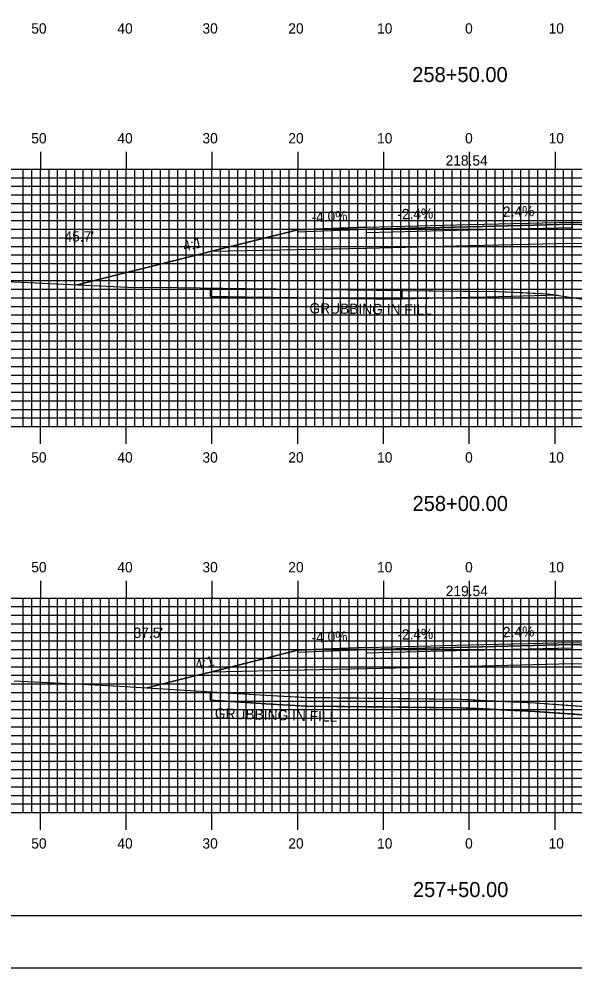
# Model space of a CAD drawing. Extents: x 1805471 to 1805814, y 442591 to 442811.
# Drawn here: x 1805584.2 to 1805648.9, y 442590.5 to 442701.2 of the extents above; entities that cross this region are included whole.
import ezdxf

# ---------------------------------------------------------------- set-up
doc = ezdxf.new("R2010")
doc.units = 0
for name, color, linetype in [('ANNOTATION', 7, 'Continuous'), ('BORDER', 7, 'Continuous'), ('D_Roadway_Centerline', 7, 'Continuous'), ('D_Roadway_Centerline_Text', 7, 'Continuous'), ('D_Roadway_Edge_Shoulder', 7, 'Continuous'), ('D_Roadway_Edge_TW', 7, 'Continuous'), ('D_Roadway_Pavement', 7, 'Continuous'), ('D_Roadway_SlopeLines', 7, 'Continuous'), ('D_Roadway_SubGrade', 7, 'Continuous'), ('D_Text_Standard', 7, 'Continuous'), ('GRUBBING IN FILL', 7, 'Continuous'), ('H_V ANNOTATION', 7, 'Continuous'), ('MAJOR', 7, 'Continuous'), ('MINOR', 7, 'Continuous'), ('PLOT BOUNDARY', 7, 'Continuous'), ('S_Roadway_Centerline', 7, 'Continuous')]:
    doc.layers.add(name, color=color, linetype=linetype)

msp = doc.modelspace()

# ---------------------------------------------------------------- linework, layer by layer
at = {"layer": 'BORDER'}
msp.add_lwpolyline([(1805487.11, 442596.67), (1805807.11, 442596.67), (1805807.11, 442806.67), (1805487.11, 442806.67)], close=True, dxfattribs=at)
at = {"layer": 'D_Roadway_Centerline'}
for points in [[(1805591.01, 442670.17), (1805604.71, 442673.6), (1805606.53, 442674.05), (1805616.71, 442676.6), (1805624.71, 442676.92), (1805636.71, 442677.21), (1805648.71, 442677.49), (1805656.71, 442677.17), (1805666.88, 442674.63), (1805668.71, 442674.17), (1805688.33, 442667.63)], [(1805599.16, 442623.21), (1805604.71, 442624.6), (1805606.53, 442625.05), (1805616.71, 442627.6), (1805624.71, 442627.92), (1805636.71, 442628.21), (1805648.71, 442628.49), (1805656.71, 442628.17), (1805666.88, 442625.63), (1805668.71, 442625.17), (1805684.65, 442619.86)]]:
    msp.add_lwpolyline(points, dxfattribs=at)
at = {"layer": 'D_Roadway_Edge_Shoulder'}
for points in [[(1805624.71, 442676.92), (1805616.71, 442676.6), (1805616.71, 442676.35), (1805624.71, 442676.67)], [(1805648.71, 442677.49), (1805656.71, 442677.17), (1805656.71, 442676.92), (1805648.71, 442677.24)], [(1805648.71, 442628.49), (1805656.71, 442628.17), (1805656.71, 442627.92), (1805648.71, 442628.24)], [(1805624.71, 442627.92), (1805616.71, 442627.6), (1805616.71, 442627.35), (1805624.71, 442627.67)]]:
    msp.add_lwpolyline(points, close=True, dxfattribs=at)
at = {"layer": 'D_Roadway_Edge_TW'}
for points in [[(1805624.71, 442676.67), (1805624.71, 442676.92), (1805636.71, 442677.21), (1805648.71, 442677.49), (1805648.71, 442677.24), (1805636.71, 442676.96)], [(1805624.71, 442627.67), (1805624.71, 442627.92), (1805636.71, 442628.21), (1805648.71, 442628.49), (1805648.71, 442628.24), (1805636.71, 442627.96)]]:
    msp.add_lwpolyline(points, close=True, dxfattribs=at)
at = {"layer": 'D_Roadway_Pavement'}
for points in [[(1805624.71, 442676.25), (1805624.71, 442676.67), (1805636.71, 442676.96), (1805648.71, 442677.24), (1805648.71, 442676.83), (1805636.71, 442676.54)], [(1805624.71, 442627.25), (1805624.71, 442627.67), (1805636.71, 442627.96), (1805648.71, 442628.24), (1805648.71, 442627.83), (1805636.71, 442627.54)]]:
    msp.add_lwpolyline(points, close=True, dxfattribs=at)
at = {"layer": 'D_Roadway_SlopeLines'}
for points in [[(1805616.71, 442676.6), (1805606.53, 442674.05), (1805604.71, 442673.6), (1805591.01, 442670.17)], [(1805616.71, 442627.6), (1805606.53, 442625.05), (1805604.71, 442624.6), (1805599.16, 442623.21)]]:
    msp.add_lwpolyline(points, dxfattribs=at)
at = {"layer": 'D_Roadway_SubGrade'}
for points in [[(1805624.71, 442674.42), (1805606.53, 442674.05), (1805616.71, 442676.6), (1805616.71, 442676.35), (1805624.71, 442676.67), (1805636.71, 442676.96), (1805648.71, 442677.24), (1805656.71, 442676.92), (1805656.71, 442677.17), (1805666.88, 442674.63), (1805648.71, 442674.99), (1805636.71, 442674.71)], [(1805624.71, 442625.42), (1805606.53, 442625.05), (1805616.71, 442627.6), (1805616.71, 442627.35), (1805624.71, 442627.67), (1805636.71, 442627.96), (1805648.71, 442628.24), (1805656.71, 442627.92), (1805656.71, 442628.17), (1805666.88, 442625.63), (1805648.71, 442625.99), (1805636.71, 442625.71)]]:
    msp.add_lwpolyline(points, close=True, dxfattribs=at)
at = {"layer": 'GRUBBING IN FILL'}
for p, q in [((1805606.53, 442669.81), (1805606.53, 442668.81)), ((1805606.53, 442669.81), (1805606.53, 442668.81)), ((1805628.84, 442669.52), (1805628.84, 442668.52)), ((1805628.84, 442669.52), (1805628.84, 442668.52)), ((1805606.53, 442622.76), (1805606.53, 442621.76)), ((1805606.53, 442622.76), (1805606.53, 442621.76))]:
    msp.add_line(p, q, dxfattribs=at)
for points in [[(1805606.53, 442669.81), (1805610.57, 442669.76), (1805621.29, 442669.62), (1805628.84, 442669.52), (1805636.03, 442669.44), (1805636.71, 442669.44), (1805636.71, 442668.71), (1805628.84, 442668.52), (1805619.7, 442668.64), (1805610.55, 442668.76), (1805606.53, 442668.81)], [(1805606.53, 442669.81), (1805610.57, 442669.76), (1805621.29, 442669.62), (1805628.84, 442669.52), (1805636.03, 442669.44), (1805636.71, 442669.44), (1805636.71, 442668.71), (1805628.84, 442668.52), (1805619.7, 442668.64), (1805610.55, 442668.76), (1805606.53, 442668.81)], [(1805636.71, 442669.44), (1805640.06, 442669.41), (1805642.96, 442669.28), (1805645.87, 442669.15), (1805647.09, 442668.96), (1805638.78, 442668.76), (1805636.71, 442668.71)], [(1805636.71, 442669.44), (1805640.06, 442669.41), (1805642.96, 442669.28), (1805645.87, 442669.15), (1805647.09, 442668.96), (1805638.78, 442668.76), (1805636.71, 442668.71)], [(1805606.53, 442622.76), (1805613.64, 442622.32), (1805617.38, 442622.1), (1805626.67, 442621.99), (1805635.61, 442621.89), (1805636.71, 442621.83), (1805636.71, 442620.83), (1805635.58, 442620.89), (1805626.64, 442620.99), (1805617.7, 442621.08), (1805613.58, 442621.32), (1805606.53, 442621.76)], [(1805606.53, 442622.76), (1805613.64, 442622.32), (1805617.38, 442622.1), (1805626.67, 442621.99), (1805635.61, 442621.89), (1805636.71, 442621.83), (1805636.71, 442620.83), (1805635.58, 442620.89), (1805626.64, 442620.99), (1805617.7, 442621.08), (1805613.58, 442621.32), (1805606.53, 442621.76)], [(1805636.71, 442621.83), (1805640.01, 442621.67), (1805644.4, 442621.44), (1805649.07, 442621.12), (1805653.73, 442620.8), (1805657.78, 442620.82), (1805661.83, 442620.83), (1805665.24, 442620.69), (1805666.88, 442620.62), (1805666.88, 442619.62), (1805664.35, 442619.73), (1805661.81, 442619.83), (1805657.76, 442619.82), (1805653.7, 442619.8), (1805649.02, 442620.12), (1805644.34, 442620.45), (1805639.96, 442620.67), (1805636.71, 442620.83)], [(1805636.71, 442621.83), (1805640.01, 442621.67), (1805644.4, 442621.44), (1805649.07, 442621.12), (1805653.73, 442620.8), (1805657.78, 442620.82), (1805661.83, 442620.83), (1805665.24, 442620.69), (1805666.88, 442620.62), (1805666.88, 442619.62), (1805664.35, 442619.73), (1805661.81, 442619.83), (1805657.76, 442619.82), (1805653.7, 442619.8), (1805649.02, 442620.12), (1805644.34, 442620.45), (1805639.96, 442620.67), (1805636.71, 442620.83)]]:
    msp.add_lwpolyline(points, close=True, dxfattribs=at)
for points in [[(1805606.53, 442668.81), (1805610.55, 442668.76), (1805628.84, 442668.52)], [(1805606.53, 442668.81), (1805610.55, 442668.76), (1805628.84, 442668.52)], [(1805606.53, 442621.76), (1805613.58, 442621.32), (1805617.1, 442621.11), (1805617.34, 442621.1), (1805617.7, 442621.08), (1805635.58, 442620.89), (1805644.34, 442620.45), (1805653.7, 442619.8), (1805661.81, 442619.83), (1805666.88, 442619.62)], [(1805606.53, 442621.76), (1805613.58, 442621.32), (1805617.1, 442621.11), (1805617.34, 442621.1), (1805617.7, 442621.08), (1805635.58, 442620.89), (1805644.34, 442620.45), (1805653.7, 442619.8), (1805661.81, 442619.83), (1805666.88, 442619.62)]]:
    msp.add_lwpolyline(points, dxfattribs=at)
at = {"layer": 'MAJOR'}
for p, q in [((1805586.71, 442685.67), (1805586.71, 442683.67)), ((1805596.71, 442685.67), (1805596.71, 442683.67)), ((1805606.71, 442685.67), (1805606.71, 442683.67)), ((1805616.71, 442685.67), (1805616.71, 442683.67)), ((1805626.71, 442685.67), (1805626.71, 442683.67)), ((1805636.71, 442685.67), (1805636.71, 442683.67)), ((1805646.71, 442685.67), (1805646.71, 442683.67)), ((1805496.71, 442683.67), (1805776.71, 442683.67)), ((1805496.71, 442683.67), (1805776.71, 442683.67)), ((1805586.71, 442653.67), (1805586.71, 442683.67)), ((1805596.71, 442653.67), (1805596.71, 442683.67)), ((1805606.71, 442653.67), (1805606.71, 442683.67)), ((1805616.71, 442653.67), (1805616.71, 442683.67)), ((1805626.71, 442653.67), (1805626.71, 442683.67)), ((1805636.71, 442653.67), (1805636.71, 442683.67)), ((1805646.71, 442653.67), (1805646.71, 442683.67)), ((1805496.71, 442678.67), (1805776.71, 442678.67)), ((1805496.71, 442673.67), (1805776.71, 442673.67)), ((1805496.71, 442668.67), (1805776.71, 442668.67)), ((1805496.71, 442663.67), (1805776.71, 442663.67)), ((1805496.71, 442658.67), (1805776.71, 442658.67)), ((1805496.71, 442653.67), (1805776.71, 442653.67)), ((1805496.71, 442653.67), (1805776.71, 442653.67)), ((1805586.71, 442651.66), (1805586.71, 442653.67)), ((1805596.71, 442651.66), (1805596.71, 442653.67)), ((1805606.71, 442651.66), (1805606.71, 442653.67)), ((1805616.71, 442651.66), (1805616.71, 442653.67)), ((1805626.71, 442651.66), (1805626.71, 442653.67)), ((1805636.71, 442651.66), (1805636.71, 442653.67)), ((1805646.71, 442651.66), (1805646.71, 442653.67)), ((1805586.71, 442635.67), (1805586.71, 442633.67)), ((1805596.71, 442635.67), (1805596.71, 442633.67)), ((1805606.71, 442635.67), (1805606.71, 442633.67)), ((1805616.71, 442635.67), (1805616.71, 442633.67)), ((1805626.71, 442635.67), (1805626.71, 442633.67)), ((1805636.71, 442635.67), (1805636.71, 442633.67)), ((1805646.71, 442635.67), (1805646.71, 442633.67)), ((1805496.71, 442633.67), (1805776.71, 442633.67)), ((1805496.71, 442633.67), (1805776.71, 442633.67)), ((1805586.71, 442608.67), (1805586.71, 442633.67)), ((1805596.71, 442608.67), (1805596.71, 442633.67)), ((1805606.71, 442608.67), (1805606.71, 442633.67)), ((1805616.71, 442608.67), (1805616.71, 442633.67)), ((1805626.71, 442608.67), (1805626.71, 442633.67)), ((1805636.71, 442608.67), (1805636.71, 442633.67)), ((1805646.71, 442608.67), (1805646.71, 442633.67)), ((1805496.71, 442628.67), (1805776.71, 442628.67)), ((1805496.71, 442623.67), (1805776.71, 442623.67)), ((1805496.71, 442618.67), (1805776.71, 442618.67)), ((1805496.71, 442613.67), (1805776.71, 442613.67)), ((1805496.71, 442608.67), (1805776.71, 442608.67)), ((1805496.71, 442608.67), (1805776.71, 442608.67)), ((1805586.71, 442606.66), (1805586.71, 442608.67)), ((1805596.71, 442606.66), (1805596.71, 442608.67)), ((1805606.71, 442606.66), (1805606.71, 442608.67)), ((1805616.71, 442606.66), (1805616.71, 442608.67)), ((1805626.71, 442606.66), (1805626.71, 442608.67)), ((1805636.71, 442606.66), (1805636.71, 442608.67)), ((1805646.71, 442606.66), (1805646.71, 442608.67))]:
    msp.add_line(p, q, dxfattribs=at)
at = {"layer": 'MINOR'}
for p, q in [((1805584.71, 442653.67), (1805584.71, 442683.67)), ((1805585.71, 442653.67), (1805585.71, 442683.67)), ((1805587.71, 442653.67), (1805587.71, 442683.67)), ((1805588.71, 442653.67), (1805588.71, 442683.67)), ((1805589.71, 442653.67), (1805589.71, 442683.67)), ((1805590.71, 442653.67), (1805590.71, 442683.67)), ((1805591.71, 442653.67), (1805591.71, 442683.67)), ((1805592.71, 442653.67), (1805592.71, 442683.67)), ((1805593.71, 442653.67), (1805593.71, 442683.67)), ((1805594.71, 442653.67), (1805594.71, 442683.67)), ((1805595.71, 442653.67), (1805595.71, 442683.67)), ((1805597.71, 442653.67), (1805597.71, 442683.67)), ((1805598.71, 442653.67), (1805598.71, 442683.67)), ((1805599.71, 442653.67), (1805599.71, 442683.67)), ((1805600.71, 442653.67), (1805600.71, 442683.67)), ((1805601.71, 442653.67), (1805601.71, 442683.67)), ((1805602.71, 442653.67), (1805602.71, 442683.67)), ((1805603.71, 442653.67), (1805603.71, 442683.67)), ((1805604.71, 442653.67), (1805604.71, 442683.67)), ((1805605.71, 442653.67), (1805605.71, 442683.67)), ((1805607.71, 442653.67), (1805607.71, 442683.67)), ((1805608.71, 442653.67), (1805608.71, 442683.67)), ((1805609.71, 442653.67), (1805609.71, 442683.67)), ((1805610.71, 442653.67), (1805610.71, 442683.67)), ((1805611.71, 442653.67), (1805611.71, 442683.67)), ((1805612.71, 442653.67), (1805612.71, 442683.67)), ((1805613.71, 442653.67), (1805613.71, 442683.67)), ((1805614.71, 442653.67), (1805614.71, 442683.67)), ((1805615.71, 442653.67), (1805615.71, 442683.67)), ((1805617.71, 442653.67), (1805617.71, 442683.67)), ((1805618.71, 442653.67), (1805618.71, 442683.67)), ((1805619.71, 442653.67), (1805619.71, 442683.67)), ((1805620.71, 442653.67), (1805620.71, 442683.67)), ((1805621.71, 442653.67), (1805621.71, 442683.67)), ((1805622.71, 442653.67), (1805622.71, 442683.67)), ((1805623.71, 442653.67), (1805623.71, 442683.67)), ((1805624.71, 442653.67), (1805624.71, 442683.67)), ((1805625.71, 442653.67), (1805625.71, 442683.67)), ((1805627.71, 442653.67), (1805627.71, 442683.67)), ((1805628.71, 442653.67), (1805628.71, 442683.67)), ((1805629.71, 442653.67), (1805629.71, 442683.67)), ((1805630.71, 442653.67), (1805630.71, 442683.67)), ((1805631.71, 442653.67), (1805631.71, 442683.67)), ((1805632.71, 442653.67), (1805632.71, 442683.67)), ((1805633.71, 442653.67), (1805633.71, 442683.67)), ((1805634.71, 442653.67), (1805634.71, 442683.67)), ((1805635.71, 442653.67), (1805635.71, 442683.67)), ((1805637.71, 442653.67), (1805637.71, 442683.67)), ((1805638.71, 442653.67), (1805638.71, 442683.67)), ((1805639.71, 442653.67), (1805639.71, 442683.67)), ((1805640.71, 442653.67), (1805640.71, 442683.67)), ((1805641.71, 442653.67), (1805641.71, 442683.67)), ((1805642.71, 442653.67), (1805642.71, 442683.67)), ((1805643.71, 442653.67), (1805643.71, 442683.67)), ((1805644.71, 442653.67), (1805644.71, 442683.67)), ((1805645.71, 442653.67), (1805645.71, 442683.67)), ((1805647.71, 442653.67), (1805647.71, 442683.67)), ((1805648.71, 442653.67), (1805648.71, 442683.67)), ((1805496.71, 442682.67), (1805776.71, 442682.67)), ((1805496.71, 442681.67), (1805776.71, 442681.67)), ((1805496.71, 442680.67), (1805776.71, 442680.67)), ((1805496.71, 442679.67), (1805776.71, 442679.67)), ((1805496.71, 442677.67), (1805776.71, 442677.67)), ((1805496.71, 442676.67), (1805776.71, 442676.67)), ((1805496.71, 442675.67), (1805776.71, 442675.67)), ((1805496.71, 442674.67), (1805776.71, 442674.67)), ((1805496.71, 442672.67), (1805776.71, 442672.67)), ((1805496.71, 442671.67), (1805776.71, 442671.67)), ((1805496.71, 442670.67), (1805776.71, 442670.67)), ((1805496.71, 442669.67), (1805776.71, 442669.67)), ((1805496.71, 442667.67), (1805776.71, 442667.67)), ((1805496.71, 442666.67), (1805776.71, 442666.67)), ((1805496.71, 442665.67), (1805776.71, 442665.67)), ((1805496.71, 442664.67), (1805776.71, 442664.67)), ((1805496.71, 442662.67), (1805776.71, 442662.67)), ((1805496.71, 442661.67), (1805776.71, 442661.67)), ((1805496.71, 442660.67), (1805776.71, 442660.67)), ((1805496.71, 442659.67), (1805776.71, 442659.67)), ((1805496.71, 442657.67), (1805776.71, 442657.67)), ((1805496.71, 442656.67), (1805776.71, 442656.67)), ((1805496.71, 442655.67), (1805776.71, 442655.67)), ((1805496.71, 442654.67), (1805776.71, 442654.67)), ((1805584.71, 442608.67), (1805584.71, 442633.67)), ((1805585.71, 442608.67), (1805585.71, 442633.67)), ((1805587.71, 442608.67), (1805587.71, 442633.67)), ((1805588.71, 442608.67), (1805588.71, 442633.67)), ((1805589.71, 442608.67), (1805589.71, 442633.67)), ((1805590.71, 442608.67), (1805590.71, 442633.67)), ((1805591.71, 442608.67), (1805591.71, 442633.67)), ((1805592.71, 442608.67), (1805592.71, 442633.67)), ((1805593.71, 442608.67), (1805593.71, 442633.67)), ((1805594.71, 442608.67), (1805594.71, 442633.67)), ((1805595.71, 442608.67), (1805595.71, 442633.67)), ((1805597.71, 442608.67), (1805597.71, 442633.67)), ((1805598.71, 442608.67), (1805598.71, 442633.67)), ((1805599.71, 442608.67), (1805599.71, 442633.67)), ((1805600.71, 442608.67), (1805600.71, 442633.67)), ((1805601.71, 442608.67), (1805601.71, 442633.67)), ((1805602.71, 442608.67), (1805602.71, 442633.67)), ((1805603.71, 442608.67), (1805603.71, 442633.67)), ((1805604.71, 442608.67), (1805604.71, 442633.67)), ((1805605.71, 442608.67), (1805605.71, 442633.67)), ((1805607.71, 442608.67), (1805607.71, 442633.67)), ((1805608.71, 442608.67), (1805608.71, 442633.67)), ((1805609.71, 442608.67), (1805609.71, 442633.67)), ((1805610.71, 442608.67), (1805610.71, 442633.67)), ((1805611.71, 442608.67), (1805611.71, 442633.67)), ((1805612.71, 442608.67), (1805612.71, 442633.67)), ((1805613.71, 442608.67), (1805613.71, 442633.67)), ((1805614.71, 442608.67), (1805614.71, 442633.67)), ((1805615.71, 442608.67), (1805615.71, 442633.67)), ((1805617.71, 442608.67), (1805617.71, 442633.67)), ((1805618.71, 442608.67), (1805618.71, 442633.67)), ((1805619.71, 442608.67), (1805619.71, 442633.67)), ((1805620.71, 442608.67), (1805620.71, 442633.67)), ((1805621.71, 442608.67), (1805621.71, 442633.67)), ((1805622.71, 442608.67), (1805622.71, 442633.67)), ((1805623.71, 442608.67), (1805623.71, 442633.67)), ((1805624.71, 442608.67), (1805624.71, 442633.67)), ((1805625.71, 442608.67), (1805625.71, 442633.67)), ((1805627.71, 442608.67), (1805627.71, 442633.67)), ((1805628.71, 442608.67), (1805628.71, 442633.67)), ((1805629.71, 442608.67), (1805629.71, 442633.67)), ((1805630.71, 442608.67), (1805630.71, 442633.67)), ((1805631.71, 442608.67), (1805631.71, 442633.67)), ((1805632.71, 442608.67), (1805632.71, 442633.67)), ((1805633.71, 442608.67), (1805633.71, 442633.67)), ((1805634.71, 442608.67), (1805634.71, 442633.67)), ((1805635.71, 442608.67), (1805635.71, 442633.67)), ((1805637.71, 442608.67), (1805637.71, 442633.67)), ((1805638.71, 442608.67), (1805638.71, 442633.67)), ((1805639.71, 442608.67), (1805639.71, 442633.67)), ((1805640.71, 442608.67), (1805640.71, 442633.67)), ((1805641.71, 442608.67), (1805641.71, 442633.67)), ((1805642.71, 442608.67), (1805642.71, 442633.67)), ((1805643.71, 442608.67), (1805643.71, 442633.67)), ((1805644.71, 442608.67), (1805644.71, 442633.67)), ((1805645.71, 442608.67), (1805645.71, 442633.67)), ((1805647.71, 442608.67), (1805647.71, 442633.67)), ((1805648.71, 442608.67), (1805648.71, 442633.67)), ((1805496.71, 442632.67), (1805776.71, 442632.67)), ((1805496.71, 442631.67), (1805776.71, 442631.67)), ((1805496.71, 442630.67), (1805776.71, 442630.67)), ((1805496.71, 442629.67), (1805776.71, 442629.67)), ((1805496.71, 442627.67), (1805776.71, 442627.67)), ((1805496.71, 442626.67), (1805776.71, 442626.67)), ((1805496.71, 442625.67), (1805776.71, 442625.67)), ((1805496.71, 442624.67), (1805776.71, 442624.67)), ((1805496.71, 442622.67), (1805776.71, 442622.67)), ((1805496.71, 442621.67), (1805776.71, 442621.67)), ((1805496.71, 442620.67), (1805776.71, 442620.67)), ((1805496.71, 442619.67), (1805776.71, 442619.67)), ((1805496.71, 442617.67), (1805776.71, 442617.67)), ((1805496.71, 442616.67), (1805776.71, 442616.67)), ((1805496.71, 442615.67), (1805776.71, 442615.67)), ((1805496.71, 442614.67), (1805776.71, 442614.67)), ((1805496.71, 442612.67), (1805776.71, 442612.67)), ((1805496.71, 442611.67), (1805776.71, 442611.67)), ((1805496.71, 442610.67), (1805776.71, 442610.67)), ((1805496.71, 442609.67), (1805776.71, 442609.67))]:
    msp.add_line(p, q, dxfattribs=at)
at = {"layer": 'PLOT BOUNDARY'}
msp.add_lwpolyline([(1805470.92, 442590.55), (1805810.92, 442590.55), (1805810.92, 442810.55), (1805470.92, 442810.55)], close=True, dxfattribs=at)
at = {"layer": 'S_Roadway_Centerline'}
for points in [[(1805496.71, 442674.61), (1805505.87, 442674.02), (1805510.39, 442673.87), (1805525.71, 442673.8), (1805528.34, 442673.78), (1805550.84, 442672.02), (1805552.54, 442671.99), (1805554.11, 442671.93), (1805564.12, 442671.62), (1805575.81, 442670.91), (1805576.88, 442670.84), (1805596.88, 442669.9), (1805598.36, 442669.89), (1805600.11, 442669.9), (1805610.57, 442669.76), (1805632, 442669.48), (1805640.06, 442669.41), (1805645.87, 442669.15), (1805651.44, 442668.26), (1805660.58, 442667.99), (1805669.4, 442668.58), (1805677.43, 442668.19), (1805697.5, 442667.16)], [(1805583.63, 442624.03), (1805593.85, 442623.53), (1805596.58, 442623.37), (1805613.64, 442622.32), (1805617.16, 442622.11), (1805617.38, 442622.1), (1805617.72, 442622.08), (1805635.61, 442621.89), (1805644.4, 442621.44), (1805653.73, 442620.8), (1805661.83, 442620.83), (1805668.65, 442620.55), (1805676.66, 442620.03), (1805694.37, 442619.66), (1805700.06, 442619.38)]]:
    msp.add_lwpolyline(points, dxfattribs=at)

# ---------------------------------------------------------------- texts
at = {"layer": 'ANNOTATION'}
for s, rotation, p in [('-2.4%', 1.3748, (1805628.33, 442677.81)), ('2.4%', 1.3748, (1805640.65, 442678.1)), ('-4.0%', 2.2906, (1805618.34, 442677.47)), ('4:1', 14.0362, (1805603.49, 442674.06)), ('2.4%', 1.3748, (1805640.65, 442629.1)), ('-4.0%', 2.2906, (1805618.34, 442628.47)), ('-2.4%', 1.3748, (1805628.33, 442628.81)), ('4:1', 14.0362, (1805604.91, 442625.28))]:
    msp.add_text(s, height=1.2, rotation=rotation, dxfattribs=at).set_placement(p)
at = {"layer": 'D_Roadway_Centerline'}
for s, p in [('C', (1805636.7, 442677.21)), ('L', (1805636.71, 442677.2)), ('C', (1805636.7, 442628.21)), ('L', (1805636.71, 442628.2))]:
    msp.add_text(s, height=0.0146, dxfattribs=at).set_placement(p)
at = {"layer": 'D_Roadway_Centerline_Text'}
for s, p in [('218.54', (1805633.95, 442684.08)), ('219.54', (1805633.97, 442633.9))]:
    msp.add_text(s, height=1.2, dxfattribs=at).set_placement(p)
at = {"layer": 'D_Text_Standard'}
for s, p in [("45.7'", (1805589.52, 442675.23)), ("37.5'", (1805597.57, 442629.03))]:
    msp.add_text(s, height=1.2, dxfattribs=at).set_placement(p)
at = {"layer": 'GRUBBING IN FILL'}
for rotation, p in [(359.3278, (1805618.07, 442666.85)), (358.41, (1805607.03, 442619.64))]:
    msp.add_text('GRUBBING IN FILL', height=1.2, rotation=rotation, dxfattribs=at).set_placement(p)
at = {"layer": 'H_V ANNOTATION'}
for s, height, p in [('50', 1.2, (1805585.64, 442699.47)), ('40', 1.2, (1805595.68, 442699.47)), ('30', 1.2, (1805605.6, 442699.47)), ('20', 1.2, (1805615.61, 442699.47)), ('10', 1.2, (1805625.96, 442699.47)), ('0', 1.2, (1805636.22, 442699.47)), ('10', 1.2, (1805645.96, 442699.47)), ('258+50.00', 1.75, (1805630.06, 442693.82)), ('50', 1.2, (1805585.64, 442686.67)), ('40', 1.2, (1805595.68, 442686.67)), ('30', 1.2, (1805605.6, 442686.67)), ('20', 1.2, (1805615.61, 442686.67)), ('10', 1.2, (1805625.96, 442686.67)), ('0', 1.2, (1805636.22, 442686.67)), ('10', 1.2, (1805645.96, 442686.67)), ('50', 1.2, (1805585.64, 442649.47)), ('40', 1.2, (1805595.68, 442649.47)), ('30', 1.2, (1805605.6, 442649.47)), ('20', 1.2, (1805615.61, 442649.47)), ('10', 1.2, (1805625.96, 442649.47)), ('0', 1.2, (1805636.22, 442649.47)), ('10', 1.2, (1805645.96, 442649.47)), ('258+00.00', 1.75, (1805630.09, 442643.82)), ('50', 1.2, (1805585.64, 442636.67)), ('40', 1.2, (1805595.68, 442636.67)), ('30', 1.2, (1805605.6, 442636.67)), ('20', 1.2, (1805615.61, 442636.67)), ('10', 1.2, (1805625.96, 442636.67)), ('0', 1.2, (1805636.22, 442636.67)), ('10', 1.2, (1805645.96, 442636.67)), ('50', 1.2, (1805585.64, 442604.47)), ('40', 1.2, (1805595.68, 442604.47)), ('30', 1.2, (1805605.6, 442604.47)), ('20', 1.2, (1805615.61, 442604.47)), ('10', 1.2, (1805625.96, 442604.47)), ('0', 1.2, (1805636.22, 442604.47)), ('10', 1.2, (1805645.96, 442604.47)), ('257+50.00', 1.75, (1805630.14, 442598.82))]:
    msp.add_text(s, height=height, dxfattribs=at).set_placement(p)

doc.saveas('drawing.dxf')
